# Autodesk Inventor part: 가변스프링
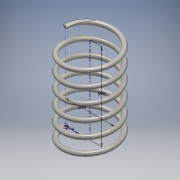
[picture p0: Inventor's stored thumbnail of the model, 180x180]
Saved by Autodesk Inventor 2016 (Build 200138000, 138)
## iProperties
Created: 2018-11
Part Number: 가변스프링
Material: 스테인레스 스틸
Document SubType Name: Modeling
Designer: user
Mass: 84.2201 g
Surface Area: 106.448 cm^2
Volume: 10.5275 cm^3
Density: 8 g/cm^3
Appearance: 반연마
Author: user
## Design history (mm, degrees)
sketch "스케치1"
  geometry: L1 (0, 0)-(22.5, 0); L2 (22.5, 0)-(22.5, 67.25); L3 (22.5, 67.25)-(0, 67.25); L4 (0, 67.25)-(0, 0); C1 r 2 at (22.5, 0)
  constraints: 8 end point, 2 parallel, 1 centre point, 1 coincident, 1 horizontal, 1 perpendicular
  dimensions: "d0" = 4 diameter of C1; "d1" = 45 diameter of L2 L4; "d2" = 67.25 distance of L3.end L1.start (derived)
feature "코일1" sketch "스케치1" pitch "d3" = 10; turns "d5" = 6; dims "d4" = 67.25 (= d2), "d6" = 0, angle "d7" = 90 deg, angle "d8" = 90 deg, "d9" = 0, "d10" = 0
sketch "스케치2"
  geometry: L1 (44.611, 0)-(-44.611, 0); L2 (-44.611, 0)-(-44.611, 67.25); L3 (-44.611, 67.25)-(44.611, 67.25); L4 (44.611, 67.25)-(44.611, 0); 2 further points
  constraints: 8 end point, 2 parallel, 1 coincident, 1 horizontal, 1 midpoint, 1 perpendicular
  dimensions: "d11" = 67.25 distance of L3.end L1.start (= d2)
extrude "돌출1" sketch "스케치2" stored distance "d12" = 100; taper "d13" = 0 deg
node "솔리드1"
